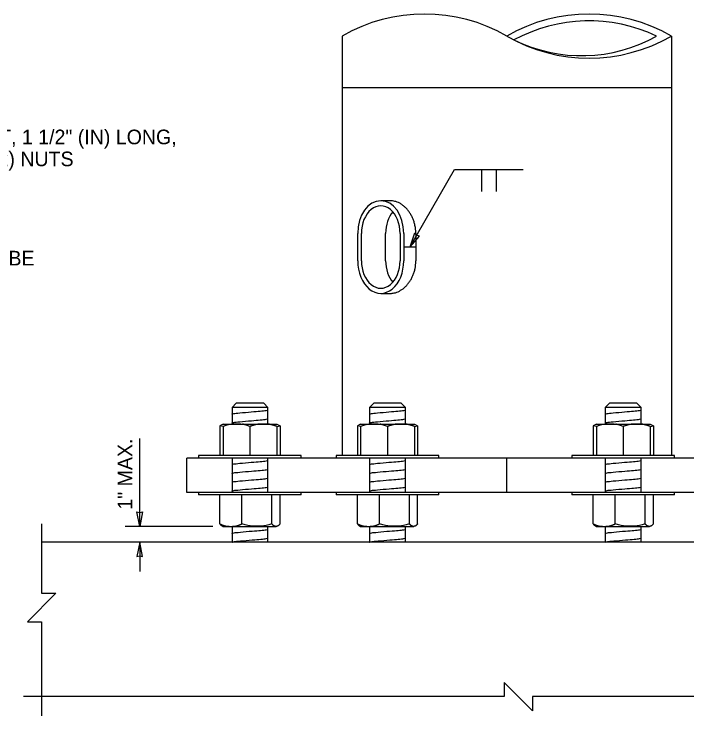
# Model space of a CAD drawing. Extents: x 99862 to 104211, y 98939 to 111076.
# Drawn here: x 101800 to 102536, y 109373 to 110140 of the extents above; entities that cross this region are included whole.
import ezdxf

# ---------------------------------------------------------------- set-up
doc = ezdxf.new("R2010")
doc.units = 0
for name, color, linetype in [('Level 10', 7, 'Continuous'), ('Level 15', 7, 'Continuous'), ('Level 2', 7, 'Continuous'), ('Level 20', 7, 'Continuous'), ('Level 3', 7, 'Continuous'), ('Level 62', 7, 'Continuous'), ('Level 9', 7, 'Continuous')]:
    doc.layers.add(name, color=color, linetype=linetype)

msp = doc.modelspace()

# ---------------------------------------------------------------- linework, layer by layer
at = {"layer": 'Level 10'}
for p, q in [((102311.78, 109970.12), (102311.78, 109946.12)), ((102327.78, 109970.12), (102327.78, 109946.12))]:
    msp.add_line(p, q, dxfattribs=at)
at = {"layer": 'Level 15'}
for p, q in [((102233.25, 109885.27), (102282.24, 109970.12)), ((102282.24, 109970.12), (102357.33, 109970.12)), ((101937.77, 109579.95), (101937.77, 109675.95)), ((102017.88, 109579.95), (101921.77, 109579.95)), ((101937.77, 109562.6), (101937.77, 109530.6))]:
    msp.add_line(p, q, dxfattribs=at)
for points in [[(102233.25, 109885.27), (102243.78, 109897.35), (102240.75, 109898.26), (102238.44, 109900.43)], [(101937.77, 109579.95), (101934.69, 109595.68), (101937.77, 109594.95), (101940.86, 109595.68)], [(101937.77, 109562.6), (101934.69, 109546.87), (101937.77, 109547.6), (101940.86, 109546.87)]]:
    msp.add_lwpolyline(points, close=True, dxfattribs=at)
for points in [[(101830.44, 109582.6), (101830.44, 109506.75), (101845.92, 109506.75), (101814.95, 109475.77), (101830.44, 109475.77), (101830.44, 109372.69)], [(102845.72, 109393.85), (102367.65, 109393.85), (102367.65, 109378.37), (102336.68, 109409.34), (102336.68, 109393.85), (101810.64, 109393.85)]]:
    msp.add_lwpolyline(points, dxfattribs=at)
at = {"layer": 'Level 2'}
for p, q in [((102689.4, 109654.65), (101989.36, 109654.65)), ((101989.36, 109617.15), (101989.36, 109654.65)), ((102339.38, 109617.15), (102339.38, 109654.65)), ((102689.4, 109617.15), (101989.36, 109617.15))]:
    msp.add_line(p, q, dxfattribs=at)
for points in [[(102038.79, 109702.63), (102038.81, 109702.69), (102038.87, 109702.75), (102040.07, 109703.34), (102045.87, 109703.85), (102060.92, 109705.29), (102069.91, 109705.85), (102076.96, 109706.73), (102078.23, 109707.03), (102078.07, 109707.4)], [(102189.3, 109702.63), (102189.32, 109702.69), (102189.39, 109702.75), (102190.58, 109703.34), (102196.38, 109703.85), (102211.43, 109705.29), (102220.42, 109705.85), (102227.48, 109706.73), (102228.74, 109707.03), (102228.59, 109707.4)], [(102447.17, 109702.63), (102447.18, 109702.69), (102447.25, 109702.75), (102448.44, 109703.34), (102454.25, 109703.85), (102469.29, 109705.29), (102478.28, 109705.85), (102485.34, 109706.73), (102486.6, 109707.03), (102486.45, 109707.4)], [(102038.79, 109692.91), (102038.77, 109692.99), (102038.84, 109693.07), (102040.09, 109693.68), (102045.91, 109694.2), (102060.96, 109695.63), (102069.94, 109696.2), (102077.15, 109697.1), (102078.4, 109697.42), (102078.02, 109697.83)], [(102189.31, 109692.91), (102189.28, 109692.99), (102189.35, 109693.07), (102190.6, 109693.68), (102196.42, 109694.2), (102211.47, 109695.63), (102220.45, 109696.2), (102227.66, 109697.1), (102228.91, 109697.42), (102228.53, 109697.83)], [(102447.17, 109692.91), (102447.14, 109692.99), (102447.21, 109693.07), (102448.47, 109693.68), (102454.28, 109694.2), (102469.34, 109695.63), (102478.32, 109696.2), (102485.53, 109697.1), (102486.78, 109697.42), (102486.39, 109697.83)], [(102038.79, 109647.5), (102038.81, 109647.56), (102038.87, 109647.62), (102040.07, 109648.21), (102045.87, 109648.72), (102060.92, 109650.15), (102069.91, 109650.72), (102076.96, 109651.6), (102078.23, 109651.9), (102078.07, 109652.27)], [(102189.3, 109647.5), (102189.32, 109647.56), (102189.39, 109647.62), (102190.58, 109648.21), (102196.38, 109648.72), (102211.43, 109650.15), (102220.42, 109650.72), (102227.48, 109651.6), (102228.74, 109651.9), (102228.59, 109652.27)], [(102447.17, 109647.5), (102447.18, 109647.56), (102447.25, 109647.62), (102448.44, 109648.21), (102454.25, 109648.72), (102469.29, 109650.15), (102478.28, 109650.72), (102485.34, 109651.6), (102486.6, 109651.9), (102486.45, 109652.27)], [(102038.79, 109637.78), (102038.77, 109637.86), (102038.84, 109637.94), (102040.09, 109638.55), (102045.91, 109639.07), (102060.96, 109640.5), (102069.94, 109641.07), (102077.15, 109641.97), (102078.4, 109642.28), (102078.02, 109642.69)], [(102189.31, 109637.78), (102189.28, 109637.86), (102189.35, 109637.94), (102190.6, 109638.55), (102196.42, 109639.07), (102211.47, 109640.5), (102220.45, 109641.07), (102227.66, 109641.97), (102228.91, 109642.28), (102228.53, 109642.69)], [(102447.17, 109637.78), (102447.14, 109637.86), (102447.21, 109637.94), (102448.47, 109638.55), (102454.28, 109639.07), (102469.34, 109640.5), (102478.32, 109641.07), (102485.53, 109641.97), (102486.78, 109642.28), (102486.39, 109642.69)], [(102038.84, 109628.25), (102038.87, 109628.29), (102038.93, 109628.33), (102040.11, 109628.9), (102045.94, 109629.41), (102061, 109630.84), (102069.98, 109631.41), (102077.01, 109632.29), (102078.26, 109632.59), (102078.06, 109632.97)], [(102189.35, 109628.25), (102189.38, 109628.29), (102189.44, 109628.33), (102190.63, 109628.9), (102196.45, 109629.41), (102211.52, 109630.84), (102220.49, 109631.41), (102227.52, 109632.29), (102228.77, 109632.59), (102228.57, 109632.97)], [(102447.21, 109628.25), (102447.25, 109628.29), (102447.31, 109628.33), (102448.49, 109628.9), (102454.32, 109629.41), (102469.38, 109630.84), (102478.35, 109631.41), (102485.39, 109632.29), (102486.63, 109632.59), (102486.44, 109632.97)], [(102038.85, 109618.6), (102038.89, 109618.64), (102038.94, 109618.68), (102040.14, 109619.24), (102045.98, 109619.76), (102061.05, 109621.19), (102070.01, 109621.76), (102077.1, 109622.65), (102078.33, 109622.95), (102078.04, 109623.35)], [(102189.36, 109618.6), (102189.4, 109618.64), (102189.46, 109618.68), (102190.65, 109619.24), (102196.49, 109619.76), (102211.56, 109621.19), (102220.52, 109621.76), (102227.61, 109622.65), (102228.85, 109622.95), (102228.55, 109623.35)], [(102447.22, 109618.6), (102447.26, 109618.64), (102447.32, 109618.68), (102448.51, 109619.24), (102454.35, 109619.76), (102469.42, 109621.19), (102478.39, 109621.76), (102485.47, 109622.65), (102486.71, 109622.95), (102486.41, 109623.35)]]:
    msp.add_open_spline(points, degree=3, dxfattribs=at)
at = {"layer": 'Level 3'}
for p, q in [((102159.38, 110115.9), (102159.38, 109657.45)), ((102519.38, 110115.9), (102519.38, 109657.45)), ((102159.38, 110059.65), (102519.38, 110059.65)), ((102212.16, 109935.9), (102201.49, 109935.9)), ((102176.3, 109870.27), (102176.3, 109900.27)), ((102180.28, 109870.27), (102180.28, 109900.27)), ((102206.8, 109870.27), (102206.8, 109900.27)), ((102222.71, 109900.27), (102222.71, 109870.27)), ((102226.69, 109900.27), (102226.69, 109870.27)), ((102239.81, 109900.27), (102239.81, 109870.27)), ((102239.81, 109885.27), (102226.69, 109885.27)), ((102201.49, 109834.65), (102212.06, 109834.65)), ((102002.27, 109657.45), (102002.27, 109654.65)), ((102114.59, 109657.45), (102002.27, 109657.45)), ((102114.59, 109654.65), (102002.27, 109654.65)), ((102114.59, 109657.45), (102114.59, 109657.45)), ((102114.59, 109654.65), (102114.59, 109657.45)), ((102114.59, 109654.65), (102114.59, 109654.65)), ((102114.59, 109654.65), (102114.59, 109654.65)), ((102265.1, 109657.45), (102152.79, 109657.45)), ((102152.79, 109657.45), (102152.79, 109654.65)), ((102265.1, 109654.65), (102152.79, 109654.65)), ((102265.1, 109657.45), (102265.11, 109657.45)), ((102265.1, 109654.65), (102265.1, 109657.45)), ((102265.1, 109654.65), (102265.11, 109654.65)), ((102265.1, 109654.65), (102265.11, 109654.65)), ((102522.96, 109657.45), (102410.65, 109657.45)), ((102410.65, 109657.45), (102410.65, 109654.65)), ((102522.96, 109654.65), (102410.65, 109654.65)), ((102522.96, 109657.45), (102522.98, 109657.45)), ((102522.96, 109654.65), (102522.96, 109657.45)), ((102522.96, 109654.65), (102522.98, 109654.65)), ((102522.96, 109654.65), (102522.98, 109654.65)), ((102002.27, 109617.15), (102002.27, 109614.34)), ((102114.59, 109617.15), (102002.27, 109617.15)), ((102114.59, 109614.34), (102002.27, 109614.34)), ((102114.59, 109617.15), (102114.59, 109617.15)), ((102114.59, 109614.34), (102114.59, 109617.15)), ((102114.59, 109617.15), (102114.59, 109617.15)), ((102114.59, 109614.34), (102114.59, 109614.34)), ((102265.1, 109617.15), (102152.79, 109617.15)), ((102152.79, 109617.15), (102152.79, 109614.34)), ((102265.1, 109614.34), (102152.79, 109614.34)), ((102265.1, 109617.15), (102265.11, 109617.15)), ((102265.1, 109614.34), (102265.1, 109617.15)), ((102265.1, 109617.15), (102265.11, 109617.15)), ((102265.1, 109614.34), (102265.11, 109614.34)), ((102522.96, 109617.15), (102410.65, 109617.15)), ((102410.65, 109617.15), (102410.65, 109614.34)), ((102522.96, 109614.34), (102410.65, 109614.34)), ((102522.96, 109617.15), (102522.98, 109617.15)), ((102522.96, 109614.34), (102522.96, 109617.15)), ((102522.96, 109617.15), (102522.98, 109617.15)), ((102522.96, 109614.34), (102522.98, 109614.34)), ((102825.72, 109562.6), (101830.44, 109562.6))]:
    msp.add_line(p, q, dxfattribs=at)
for centre, radius, start, end in [((102249.38, 109960.01), 180, 60, 120), ((102429.38, 109960.01), 180, 60, 120), ((102429.38, 109960.01), 172.5, 64.64591, 118.46608), ((102429.38, 110271.78), 180, 240, 300), ((102421.16, 110262.57), 168.08, 243.87895, 299.23304)]:
    msp.add_arc(centre, radius, start, end, dxfattribs=at)
for centre, major_axis, start_param, end_param in [((102201.49, 109900.27), (0, 35.62), 4.712389, 7.853963), ((102201.49, 109900.27), (0, 30), 4.712389, 7.853982), ((102228.01, 109900.27), (0, 30), 0.675129, 1.570796), ((102201.49, 109900.27), (0, 35.63), 4.712389, 4.712389), ((102201.49, 109870.27), (0, 35.62), 1.570796, 4.712389), ((102201.49, 109870.27), (0, 30), 1.570796, 4.712389), ((102228.01, 109870.27), (0, 30), 1.570796, 2.466458)]:
    msp.add_ellipse(centre, major_axis=major_axis, ratio=0.707107, start_param=start_param, end_param=end_param, dxfattribs=at)
for points in [[(102239.81, 109900.27), (102239.81, 109904.22), (102239.23, 109908.21), (102238.15, 109911.93), (102237.07, 109915.65), (102235.45, 109919.19), (102233.46, 109922.28), (102231.46, 109925.4), (102229.02, 109928.14), (102226.4, 109930.28), (102223.76, 109932.44), (102220.85, 109934.05), (102217.96, 109934.96), (102216.02, 109935.58), (102214.05, 109935.89), (102212.14, 109935.89)], [(102212.1, 109834.65), (102213, 109834.65), (102213.91, 109834.72), (102214.81, 109834.85), (102217.62, 109835.27), (102220.51, 109836.35), (102223.22, 109838), (102225.95, 109839.67), (102228.57, 109841.96), (102230.84, 109844.69), (102233.15, 109847.46), (102235.15, 109850.77), (102236.64, 109854.35), (102238.14, 109857.93), (102239.15, 109861.88), (102239.58, 109865.86), (102239.73, 109867.32), (102239.81, 109868.8), (102239.81, 109870.27)]]:
    msp.add_open_spline(points, degree=3, dxfattribs=at)
at = {"layer": 'Level 62'}
for points in [[(102038.8, 109572.19), (102038.8, 109572.27), (102038.89, 109572.35), (102040.27, 109572.95), (102046.56, 109573.5), (102061.83, 109574.96), (102070.49, 109575.5), (102076.83, 109576.31), (102078.01, 109576.58), (102078.06, 109576.91)], [(102189.31, 109572.19), (102189.31, 109572.27), (102189.4, 109572.35), (102190.78, 109572.95), (102197.07, 109573.5), (102212.34, 109574.96), (102221, 109575.5), (102227.35, 109576.31), (102228.53, 109576.58), (102228.57, 109576.91)], [(102447.17, 109572.19), (102447.18, 109572.27), (102447.26, 109572.35), (102448.64, 109572.95), (102454.94, 109573.5), (102470.2, 109574.96), (102478.87, 109575.5), (102485.21, 109576.31), (102486.39, 109576.58), (102486.44, 109576.91)], [(102038.82, 109562.6), (102038.86, 109562.65), (102038.94, 109562.71), (102040.29, 109563.3), (102046.6, 109563.85), (102061.87, 109565.3), (102070.53, 109565.85), (102077.03, 109566.68), (102078.21, 109566.97), (102078.05, 109567.33)], [(102189.33, 109562.6), (102189.37, 109562.65), (102189.45, 109562.71), (102190.8, 109563.3), (102197.11, 109563.85), (102212.38, 109565.3), (102221.04, 109565.85), (102227.54, 109566.68), (102228.72, 109566.97), (102228.56, 109567.33)], [(102447.2, 109562.6), (102447.23, 109562.65), (102447.32, 109562.71), (102448.67, 109563.3), (102454.97, 109563.85), (102470.24, 109565.3), (102478.9, 109565.85), (102485.4, 109566.68), (102486.58, 109566.97), (102486.42, 109567.33)]]:
    msp.add_open_spline(points, degree=3, dxfattribs=at)
at = {"layer": 'Level 9'}
for p, q in [((102043.46, 109714.46), (102038.78, 109709.78)), ((102073.41, 109714.46), (102043.46, 109714.46)), ((102073.41, 109714.46), (102073.41, 109714.46)), ((102078.09, 109709.78), (102073.41, 109714.46)), ((102193.97, 109714.46), (102189.29, 109709.78)), ((102223.92, 109714.46), (102193.97, 109714.46)), ((102223.92, 109714.46), (102223.92, 109714.46)), ((102228.6, 109709.78), (102223.92, 109714.46)), ((102451.83, 109714.46), (102447.15, 109709.78)), ((102481.78, 109714.46), (102451.83, 109714.46)), ((102481.78, 109714.46), (102481.79, 109714.46)), ((102486.46, 109709.78), (102481.78, 109714.46)), ((102038.78, 109709.78), (102038.78, 109691.84)), ((102078.09, 109709.78), (102038.78, 109709.78)), ((102078.09, 109691.84), (102078.09, 109709.78)), ((102078.09, 109709.78), (102078.09, 109709.78)), ((102189.29, 109709.78), (102189.29, 109691.84)), ((102228.6, 109709.78), (102189.29, 109709.78)), ((102228.6, 109691.84), (102228.6, 109709.78)), ((102228.6, 109709.78), (102228.6, 109709.78)), ((102447.15, 109709.78), (102447.15, 109691.84)), ((102486.46, 109709.78), (102447.15, 109709.78)), ((102486.46, 109691.84), (102486.46, 109709.78)), ((102486.46, 109709.78), (102486.47, 109709.78)), ((102028.95, 109691.84), (102025.55, 109689.88)), ((102025.55, 109689.88), (102025.55, 109657.45)), ((102028.95, 109689.21), (102025.55, 109689.88)), ((102028.96, 109691.84), (102028.95, 109691.84)), ((102028.95, 109691.84), (102072.83, 109691.84)), ((102028.95, 109689.21), (102028.95, 109657.45)), ((102043.16, 109691.84), (102044.23, 109691.84)), ((102051.18, 109691.84), (102050.43, 109691.84)), ((102058.43, 109689.21), (102058.43, 109657.45)), ((102065.47, 109691.84), (102066.66, 109691.84)), ((102072.47, 109691.84), (102073.86, 109691.84)), ((102073.51, 109691.84), (102072.83, 109691.84)), ((102073.51, 109691.84), (102072.83, 109691.84)), ((102073.51, 109691.84), (102087.9, 109691.84)), ((102079.79, 109691.84), (102078.76, 109691.84)), ((102087.9, 109689.21), (102087.9, 109657.45)), ((102087.91, 109691.84), (102091.31, 109689.88)), ((102087.91, 109689.21), (102091.31, 109689.88)), ((102091.31, 109689.88), (102091.31, 109657.45)), ((102179.46, 109691.84), (102176.07, 109689.88)), ((102176.07, 109689.88), (102176.07, 109657.45)), ((102179.46, 109689.21), (102176.07, 109689.88)), ((102179.47, 109691.84), (102179.46, 109691.84)), ((102179.46, 109691.84), (102223.35, 109691.84)), ((102179.46, 109689.21), (102179.46, 109657.45)), ((102193.67, 109691.84), (102194.74, 109691.84)), ((102201.7, 109691.84), (102200.95, 109691.84)), ((102208.94, 109689.21), (102208.94, 109657.45)), ((102215.98, 109691.84), (102217.17, 109691.84)), ((102222.98, 109691.84), (102224.37, 109691.84)), ((102224.02, 109691.84), (102223.35, 109691.84)), ((102224.02, 109691.84), (102223.35, 109691.84)), ((102224.02, 109691.84), (102238.42, 109691.84)), ((102230.3, 109691.84), (102229.27, 109691.84)), ((102238.42, 109691.84), (102241.82, 109689.88)), ((102238.42, 109689.21), (102241.82, 109689.88)), ((102238.42, 109689.21), (102238.42, 109657.45)), ((102241.82, 109689.88), (102241.82, 109657.45)), ((102437.33, 109691.84), (102433.93, 109689.88)), ((102433.93, 109689.88), (102433.93, 109657.45)), ((102437.33, 109689.21), (102433.93, 109689.88)), ((102437.33, 109691.84), (102437.33, 109691.84)), ((102437.33, 109691.84), (102481.21, 109691.84)), ((102437.33, 109689.21), (102437.33, 109657.45)), ((102451.54, 109691.84), (102452.6, 109691.84)), ((102459.56, 109691.84), (102458.81, 109691.84)), ((102466.8, 109689.21), (102466.8, 109657.45)), ((102473.85, 109691.84), (102475.04, 109691.84)), ((102480.85, 109691.84), (102482.24, 109691.84)), ((102481.88, 109691.84), (102481.21, 109691.84)), ((102481.88, 109691.84), (102481.21, 109691.84)), ((102481.88, 109691.84), (102496.28, 109691.84)), ((102488.17, 109691.84), (102487.14, 109691.84)), ((102496.28, 109689.21), (102496.28, 109657.45)), ((102496.29, 109691.84), (102499.68, 109689.88)), ((102496.29, 109689.21), (102499.68, 109689.88)), ((102499.68, 109689.88), (102499.68, 109657.45)), ((102038.78, 109654.65), (102038.78, 109617.15)), ((102078.09, 109617.15), (102078.09, 109654.65)), ((102189.29, 109654.65), (102189.29, 109617.15)), ((102228.6, 109617.15), (102228.6, 109654.65)), ((102447.15, 109654.65), (102447.15, 109617.15)), ((102486.46, 109617.15), (102486.46, 109654.65)), ((102025.56, 109582.58), (102025.56, 109614.34)), ((102049.62, 109582.58), (102049.62, 109614.34)), ((102082.5, 109582.58), (102082.5, 109614.34)), ((102091.31, 109582.58), (102091.31, 109614.34)), ((102176.07, 109582.58), (102176.07, 109614.34)), ((102200.14, 109582.58), (102200.14, 109614.34)), ((102233.01, 109582.58), (102233.01, 109614.34)), ((102241.82, 109582.58), (102241.82, 109614.34)), ((102433.93, 109582.58), (102433.93, 109614.34)), ((102458, 109582.58), (102458, 109614.34)), ((102490.87, 109582.58), (102490.87, 109614.34)), ((102499.68, 109582.58), (102499.68, 109614.34)), ((102027.75, 109580.65), (102028.96, 109579.95)), ((102027.91, 109580.56), (102028.95, 109579.95)), ((102028.95, 109579.95), (102037.59, 109579.95)), ((102029.8, 109579.95), (102030.12, 109579.95)), ((102033.11, 109579.95), (102032.72, 109579.95)), ((102037.59, 109579.95), (102086.8, 109579.95)), ((102038.78, 109579.95), (102038.78, 109562.6)), ((102050.03, 109579.95), (102051.58, 109579.95)), ((102059.17, 109579.95), (102057.72, 109579.95)), ((102078.09, 109562.6), (102078.09, 109579.95)), ((102078.76, 109579.95), (102079.79, 109579.95)), ((102084.37, 109579.95), (102083.56, 109579.95)), ((102086.8, 109579.95), (102087.01, 109579.95)), ((102087.01, 109579.95), (102086.8, 109579.95)), ((102178.27, 109580.65), (102179.48, 109579.95)), ((102178.42, 109580.56), (102179.46, 109579.95)), ((102179.46, 109579.95), (102188.1, 109579.95)), ((102180.32, 109579.95), (102180.63, 109579.95)), ((102183.62, 109579.95), (102183.23, 109579.95)), ((102188.1, 109579.95), (102237.32, 109579.95)), ((102189.29, 109579.95), (102189.29, 109562.6)), ((102200.54, 109579.95), (102202.09, 109579.95)), ((102209.69, 109579.95), (102208.23, 109579.95)), ((102228.6, 109562.6), (102228.6, 109579.95)), ((102229.27, 109579.95), (102230.3, 109579.95)), ((102234.88, 109579.95), (102234.08, 109579.95)), ((102237.32, 109579.95), (102237.52, 109579.95)), ((102237.52, 109579.95), (102237.32, 109579.95)), ((102436.13, 109580.65), (102437.34, 109579.95)), ((102436.28, 109580.56), (102437.33, 109579.95)), ((102437.33, 109579.95), (102445.96, 109579.95)), ((102438.18, 109579.95), (102438.5, 109579.95)), ((102441.49, 109579.95), (102441.1, 109579.95)), ((102445.96, 109579.95), (102495.18, 109579.95)), ((102447.15, 109579.95), (102447.15, 109562.6)), ((102447.15, 109579.95), (102447.15, 109562.6)), ((102458.4, 109579.95), (102459.96, 109579.95)), ((102467.55, 109579.95), (102466.09, 109579.95)), ((102486.46, 109562.6), (102486.46, 109579.95)), ((102487.13, 109579.95), (102488.16, 109579.95)), ((102492.74, 109579.95), (102491.94, 109579.95)), ((102495.18, 109579.95), (102495.38, 109579.95)), ((102495.38, 109579.95), (102495.18, 109579.95))]:
    msp.add_line(p, q, dxfattribs=at)
for points, degree in [([(102058.43, 109689.21), (102053.61, 109690.82), (102048.73, 109691.84), (102038.7, 109691.85), (102033.77, 109690.82), (102028.95, 109689.21)], 3), ([(102072.83, 109691.84), (102067.94, 109691.8), (102063.13, 109690.78), (102058.43, 109689.21)], 2), ([(102087.9, 109689.21), (102083.19, 109690.79), (102078.41, 109691.8), (102073.51, 109691.84)], 2), ([(102208.94, 109689.21), (102204.13, 109690.82), (102199.24, 109691.84), (102189.22, 109691.85), (102184.28, 109690.82), (102179.46, 109689.21)], 3), ([(102223.35, 109691.84), (102218.45, 109691.8), (102213.64, 109690.78), (102208.94, 109689.21)], 2), ([(102238.42, 109689.21), (102233.7, 109690.79), (102228.92, 109691.8), (102224.02, 109691.84)], 2), ([(102466.8, 109689.21), (102461.99, 109690.82), (102457.1, 109691.84), (102447.08, 109691.85), (102442.15, 109690.82), (102437.33, 109689.21)], 3), ([(102481.21, 109691.84), (102476.31, 109691.8), (102471.51, 109690.78), (102466.8, 109689.21)], 2), ([(102496.28, 109689.21), (102491.57, 109690.79), (102486.79, 109691.8), (102481.88, 109691.84)], 2), ([(102025.56, 109582.58), (102026.34, 109581.71), (102027.13, 109581.01), (102027.92, 109580.55)], 2), ([(102025.56, 109582.58), (102029.47, 109580.98), (102033.52, 109579.95), (102037.59, 109579.95)], 2), ([(102037.59, 109579.95), (102041.66, 109579.95), (102045.73, 109581), (102049.62, 109582.58)], 2), ([(102082.5, 109582.58), (102077.13, 109580.98), (102071.68, 109579.96), (102060.5, 109579.95), (102055, 109580.98), (102049.62, 109582.58)], 3), ([(102086.8, 109579.95), (102085.34, 109579.99), (102083.9, 109581.02), (102082.5, 109582.58)], 2), ([(102091.31, 109582.58), (102089.9, 109581.01), (102088.47, 109579.99), (102087.01, 109579.95)], 2), ([(102176.07, 109582.58), (102176.85, 109581.71), (102177.64, 109581.01), (102178.44, 109580.55)], 2), ([(102176.07, 109582.58), (102179.98, 109580.98), (102184.03, 109579.95), (102188.1, 109579.95)], 2), ([(102188.1, 109579.95), (102192.17, 109579.95), (102196.24, 109581), (102200.14, 109582.58)], 2), ([(102233.01, 109582.58), (102227.64, 109580.98), (102222.2, 109579.96), (102211.01, 109579.95), (102205.51, 109580.98), (102200.14, 109582.58)], 3), ([(102237.32, 109579.95), (102235.85, 109579.99), (102234.42, 109581.02), (102233.01, 109582.58)], 2), ([(102241.82, 109582.58), (102240.41, 109581.01), (102238.98, 109579.99), (102237.52, 109579.95)], 2), ([(102433.93, 109582.58), (102434.71, 109581.71), (102435.5, 109581.01), (102436.3, 109580.55)], 2), ([(102433.93, 109582.58), (102437.85, 109580.98), (102441.89, 109579.95), (102445.96, 109579.95)], 2), ([(102445.96, 109579.95), (102450.03, 109579.95), (102454.11, 109581), (102458, 109582.58)], 2), ([(102490.87, 109582.58), (102485.51, 109580.98), (102480.06, 109579.96), (102468.88, 109579.95), (102463.37, 109580.98), (102458, 109582.58)], 3), ([(102495.18, 109579.95), (102493.72, 109579.99), (102492.28, 109581.02), (102490.87, 109582.58)], 2), ([(102499.68, 109582.58), (102498.27, 109581.01), (102496.85, 109579.99), (102495.38, 109579.95)], 2)]:
    msp.add_open_spline(points, degree=degree, dxfattribs=at)

# ---------------------------------------------------------------- texts
at = {"layer": 'Level 20'}
for s, p in [('1/2" (IN) DIAM. STEEL BOLT, 1 1/2" (IN) LONG,', (101517.2, 109997.65)), ('WITH (2) WASHERS AND (2) NUTS ', (101517.2, 109973.65)), ('INSIDE EDGES SHALL BE', (101562.34, 109865.17))]:
    msp.add_text(s, height=16, dxfattribs=at).set_placement(p)
msp.add_text('1" MAX.', height=16, rotation=90, dxfattribs=at).set_placement((101929.77, 109598.2))

doc.saveas('drawing.dxf')
